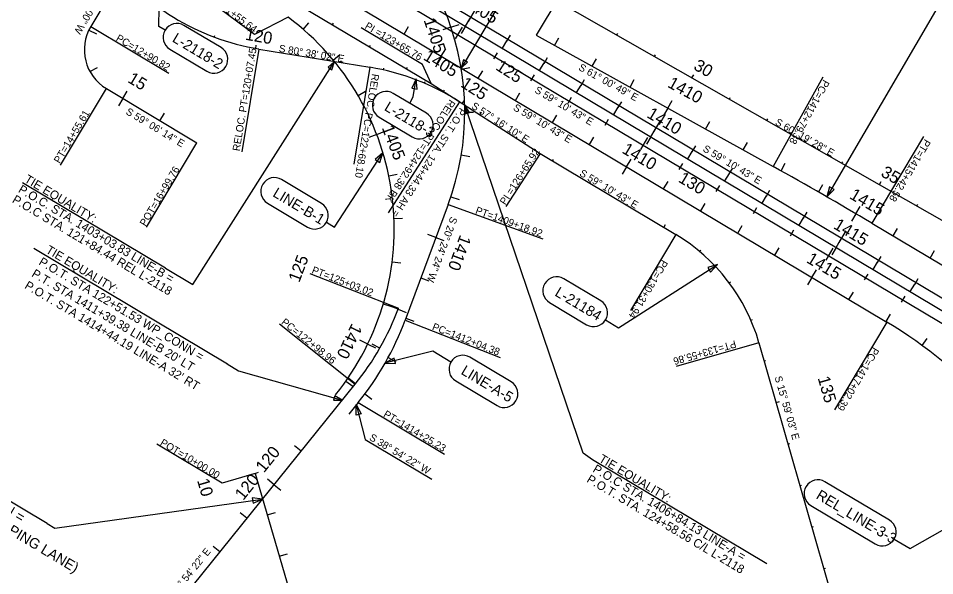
# Model space of a CAD drawing. Extents: x 2339300 to 2355400, y 360879 to 381052.
# Drawn here: x 2345923 to 2348046, y 368208 to 369499 of the extents above; entities that cross this region are included whole.
import ezdxf

# ---------------------------------------------------------------- set-up
doc = ezdxf.new("R2010")
doc.units = 0
for name, color, linetype in [('RD_HC_Cl', 7, 'Continuous'), ('RD_HC_CL_Rel', 7, 'Continuous'), ('RD_HC_Data', 7, 'Continuous'), ('RD_HC_Data_Rel', 7, 'Continuous'), ('RD_HC_Data_Tic', 7, 'Continuous'), ('RD_HC_Data_Tic_Rel', 7, 'Continuous'), ('RD_HC_TX_Rel_Sta50', 7, 'Continuous'), ('RD_HC_TX_Sta50', 7, 'Continuous'), ('RD_PD_Final_TX', 7, 'Continuous')]:
    doc.layers.add(name, color=color, linetype=linetype)

msp = doc.modelspace()

# ---------------------------------------------------------------- linework, layer by layer
at = {"layer": 'RD_HC_Cl'}
for p, q in [((2346281.6, 369885.4), (2351112.4, 367003.2)), ((2346202.2, 369752.3), (2346879.4, 369348.3)), ((2346240, 369730), (2346091, 369480.3)), ((2347125.2, 369566.1), (2348362.6, 368861)), ((2346879.4, 369348.3), (2347131.9, 369186)), ((2346127.3, 369336.4), (2346336.8, 369211)), ((2347131.9, 369186), (2347446.2, 368998.5)), ((2346919, 369067.9), (2346819.4, 368800.4)), ((2347639.2, 368747.8), (2347994.6, 367509.7)), ((2346059.3, 367853.2), (2346703.6, 368651.5)), ((2346710.6, 368609.3), (2346688.9, 368582.4)), ((2346471.7, 368445.2), (2346829.6, 367219.9))]:
    msp.add_line(p, q, dxfattribs=at)
for centre, radius, start, end in [((2346341.6, 369282.7), 616, 339.5935, 61.7249), ((2346182, 369011.6), 612, 321.0938, 53.1918), ((2346181.2, 369426.5), 105, 149.1832, 239.1039), ((2347225.9, 368629.2), 430, 16.0174, 59.1785), ((2346211.8, 369048.5), 632, 321.0938, 339.5935), ((2346178.4, 369038.9), 684, 321.0938, 339.5935)]:
    msp.add_arc(centre, radius, start, end, dxfattribs=at)
at = {"layer": 'RD_HC_CL_Rel'}
for p, q in [((2346294.5, 369907), (2348311.8, 368703.5)), ((2346268.7, 369863.8), (2348286, 368660.2)), ((2346236.3, 369809.5), (2347935.6, 368795.6)), ((2347122.8, 369460.4), (2347672.4, 369155.9)), ((2346480.4, 369428.2), (2346737.6, 369385.8)), ((2347900.5, 369024.7), (2348345.9, 368759))]:
    msp.add_line(p, q, dxfattribs=at)
for centre, radius, start, end in [((2346569.9, 369970.9), 550, 216.3291, 260.6339), ((2346648.1, 368843.1), 550, 57.2694, 80.6339), ((2343690.2, 361967.9), 8217.3, 59.17851, 61.01367), ((2347423.3, 367936.8), 1000, 22.7108, 59.1785)]:
    msp.add_arc(centre, radius, start, end, dxfattribs=at)
at = {"layer": 'RD_HC_Data'}
for p, q in [((2346091, 369480.3), (2346272.3, 369372.1)), ((2346392.9, 369431.6), (2346307, 369482.8)), ((2346274.2, 369427.8), (2346360.1, 369376.6)), ((2346021.1, 369158.8), (2346127.3, 369336.4)), ((2346868.7, 369279.4), (2346791.7, 369325.3)), ((2346759, 369270.3), (2346835.9, 369224.4)), ((2346220, 369015.9), (2346336.8, 369211)), ((2347131.9, 369186), (2347053, 369063.3)), ((2346625.8, 369070.7), (2346533.3, 369125.9)), ((2346500.5, 369070.9), (2346593, 369015.7)), ((2346919, 369067.9), (2347138.3, 368988.5)), ((2347446.2, 368998.5), (2347341.3, 368822.7)), ((2346598.4, 368908.4), (2346804.1, 368828.1)), ((2347272.7, 368844.6), (2347186.9, 368895.8)), ((2347154.1, 368840.9), (2347239.9, 368789.6)), ((2346528.2, 368791.8), (2346703.6, 368651.5)), ((2346819.4, 368800.4), (2347039.4, 368713.6)), ((2347639.2, 368747.8), (2347447.5, 368692.8)), ((2347065.1, 368657.1), (2346969.4, 368714.2)), ((2346936.6, 368659.2), (2347032.3, 368602.1)), ((2345990, 368328.8), (2345468, 368640.3)), ((2346710.6, 368609.3), (2346910.7, 368489.9)), ((2347941.4, 368336.9), (2347792.1, 368426)), ((2347759.3, 368371), (2347908.6, 368282))]:
    msp.add_line(p, q, dxfattribs=at)
for points in [[(2348132.2, 369559.9), (2348088.1, 369586.2), (2347796.2, 369085.9)], [(2346548.7, 369501.6), (2346470.5, 369461.8), (2346330.5, 369566.4)], [(2346263.1, 369471.7), (2346249, 369480.1), (2346249.8, 369523.6)], [(2346879.4, 369348.3), (2346859.9, 369392.4), (2346717.9, 369477.1)], [(2346830.2, 369302.3), (2346837.9, 369318.4), (2346844.8, 369359.3)], [(2346636.9, 369026.8), (2346655.9, 369015.4), (2346768, 369188)], [(2347283.8, 368800.7), (2347314, 368782.7), (2347543.3, 368929.1)], [(2346925.5, 368703.1), (2346883.5, 368728.1), (2346772.7, 368700.4)], [(2346705.6, 368604.6), (2346726.9, 368523.7), (2346881.3, 368431.6)], [(2346471.7, 368445.2), (2346395.4, 368422.5), (2346244.4, 368512.6)], [(2347952.5, 368293), (2347989.6, 368270.9), (2348287.4, 368440)], [(2345990, 368328.8), (2346008.1, 368318.1), (2346489.1, 368385.7)]]:
    msp.add_lwpolyline(points, dxfattribs=at)
for points in [[(2346847.1, 369335.4), (2346844.8, 369359.3), (2346834.8, 369337.4)], [(2346760.6, 369165.2), (2346768, 369188), (2346750.2, 369171.9)], [(2347802.6, 369109), (2347796.2, 369085.9), (2347813.3, 369102.8)], [(2347527.1, 368911.4), (2347543.3, 368929.1), (2347520.4, 368921.9)], [(2346793.7, 368712), (2346772.7, 368700.4), (2346796.7, 368700)], [(2346467, 368376.3), (2346489.1, 368385.7), (2346465.2, 368388.6)]]:
    msp.add_lwpolyline(points, close=True, dxfattribs=at)
for centre, start, end in [((2346290.6, 369455.3), 59.1784, 239.1784), ((2346376.5, 369404.1), 239.1784, 59.1784), ((2346775.4, 369297.8), 59.1784, 239.1784), ((2346852.3, 369251.9), 239.1784, 59.1784), ((2346516.9, 369098.4), 59.1784, 239.1784), ((2346609.4, 369043.2), 239.1784, 59.1784), ((2347170.5, 368868.4), 59.1784, 239.1784), ((2347256.3, 368817.1), 239.1784, 59.1784), ((2346953, 368686.7), 59.1784, 239.1784), ((2347048.7, 368629.6), 239.1784, 59.1784), ((2347775.7, 368398.5), 59.1784, 239.1784), ((2347925, 368309.4), 239.1784, 59.1784)]:
    msp.add_arc(centre, 32, start, end, dxfattribs=at)
at = {"layer": 'RD_HC_Data_Rel'}
for p, q in [((2346480.4, 369428.2), (2346441.1, 369189.9)), ((2346737.6, 369385.8), (2346700.6, 369161.6)), ((2347786.9, 369362.7), (2347672.4, 369155.9)), ((2346945.5, 369305.8), (2346780.4, 369048.9)), ((2348020.2, 369225.4), (2347900.5, 369024.7)), ((2347935.6, 368795.6), (2347814.5, 368592.6))]:
    msp.add_line(p, q, dxfattribs=at)
at = {"layer": 'RD_HC_Data_Tic'}
for p, q in [((2346959.2, 369481.1), (2346969.5, 369498.3)), ((2346086.7, 369472.2), (2346104.7, 369463.5)), ((2346583.2, 369473.7), (2346596.3, 369488.8)), ((2346651.1, 369484.4), (2346653.2, 369487.9)), ((2346925.6, 369478.8), (2346906.6, 369472.4)), ((2346925.6, 369478.8), (2346944.6, 369485.1)), ((2346959.2, 369481.1), (2346949, 369464)), ((2347310.2, 369460.7), (2347312.2, 369464.1)), ((2346737, 369433.2), (2346739.1, 369436.6)), ((2347045.1, 369429.9), (2347055.3, 369447.1)), ((2346653, 369402.3), (2346668.4, 369415.1)), ((2347397.1, 369411.2), (2347399.1, 369414.6)), ((2347131, 369378.7), (2347141.2, 369395.8)), ((2346089.2, 369375.9), (2346106.7, 369385.6)), ((2346822.9, 369382), (2346824.9, 369385.4)), ((2346949.6, 369381.8), (2346969.3, 369385)), ((2347484, 369361.6), (2347487.9, 369368.6)), ((2347216.8, 369327.4), (2347227.1, 369344.6)), ((2346165.4, 369313.6), (2346175.7, 369330.7)), ((2346710.3, 369320.5), (2346727.6, 369330.6)), ((2346908.2, 369329.8), (2346910.3, 369333.1)), ((2346165.4, 369313.6), (2346155.1, 369296.4)), ((2347570.8, 369312.1), (2347572.8, 369315.6)), ((2346957.6, 369282.2), (2346977.6, 369282.2)), ((2346992.3, 369275.7), (2346996.6, 369282.4)), ((2347302.7, 369276.2), (2347313, 369293.4)), ((2346251.2, 369262.2), (2346261.5, 369279.4)), ((2347657.7, 369262.6), (2347659.7, 369266.1)), ((2346753.5, 369230.4), (2346772.2, 369237.6)), ((2347388.6, 369225), (2347398.8, 369242.1)), ((2346753.5, 369230.4), (2346734.9, 369223.3)), ((2347076.4, 369221.6), (2347078.6, 369225)), ((2347388.6, 369225), (2347378.3, 369207.8)), ((2347744.6, 369213.1), (2347746.6, 369216.6)), ((2346949.4, 369182.7), (2346969.2, 369179.4)), ((2347474.5, 369173.7), (2347484.7, 369190.9)), ((2347161.1, 369168.5), (2347163.2, 369172)), ((2347831.5, 369163.6), (2347833.5, 369167.1)), ((2346781.5, 369134.5), (2346801.1, 369138.5)), ((2347560.3, 369122.5), (2347570.6, 369139.7)), ((2347247, 369117.3), (2347249.1, 369120.7)), ((2347918.4, 369114.1), (2347922.3, 369121.1)), ((2346925.3, 369085.7), (2346944.2, 369079.4)), ((2347332.9, 369066.1), (2347334.9, 369069.5)), ((2347646.2, 369071.2), (2347656.5, 369088.4)), ((2348005.3, 369064.6), (2348007.2, 369068.1)), ((2346793.5, 369035.4), (2346813.5, 369036.1)), ((2347732.1, 369020), (2347742.3, 369037.2)), ((2347418.8, 369014.8), (2347422.9, 369021.7)), ((2346890.7, 368991.9), (2346871.9, 368998.9)), ((2346890.7, 368991.9), (2346909.4, 368985)), ((2347818, 368968.8), (2347828.2, 368985.9)), ((2347501.6, 368959.1), (2347504.2, 368962.2)), ((2347818, 368968.8), (2347807.7, 368951.6)), ((2346789.3, 368935.6), (2346809.1, 368933.1)), ((2347903.9, 368917.5), (2347914.1, 368934.7)), ((2346855.8, 368898.2), (2346874.6, 368891.2)), ((2347570.3, 368886.7), (2347573.5, 368889.1)), ((2347989.7, 368866.3), (2348000, 368883.5)), ((2346768.8, 368837.8), (2346788, 368832.1)), ((2346803.1, 368825.3), (2346784.4, 368832.3)), ((2346803.1, 368825.3), (2346821.8, 368818.2)), ((2346821, 368804.5), (2346839.7, 368797.5)), ((2347620.3, 368800.4), (2347624, 368802)), ((2346732.7, 368744.6), (2346714.7, 368753.4)), ((2346732.7, 368744.6), (2346750.7, 368735.9)), ((2346760.5, 368734.9), (2346743.2, 368744.8)), ((2346779.9, 368713.4), (2346797.5, 368703.9)), ((2347651.4, 368705.4), (2347655.2, 368706.5)), ((2346704.3, 368652.4), (2346688.7, 368664.9)), ((2346682, 368658.6), (2346698.3, 368647.1)), ((2346726.1, 368629.2), (2346742.1, 368617.2)), ((2347679, 368609.3), (2347686.6, 368611.5)), ((2346578.7, 368496.7), (2346563.1, 368509.3)), ((2347706.5, 368513.2), (2347710.4, 368514.3)), ((2346471.7, 368445.2), (2346452.5, 368439.6)), ((2346471.7, 368445.2), (2346480, 368447.7)), ((2346515.8, 368418.9), (2346500.3, 368431.5)), ((2346515.8, 368418.9), (2346531.4, 368406.3)), ((2347734.1, 368417), (2347738, 368418.2)), ((2346453, 368341.1), (2346437.5, 368353.6)), ((2346499.7, 368349.2), (2346518.9, 368354.8)), ((2347761.7, 368320.9), (2347765.6, 368322)), ((2346390.2, 368263.3), (2346374.7, 368275.8)), ((2346527.7, 368253.2), (2346546.9, 368258.9)), ((2347789.3, 368224.8), (2347793.2, 368225.9))]:
    msp.add_line(p, q, dxfattribs=at)
at = {"layer": 'RD_HC_Data_Tic_Rel'}
for p, q in [((2346966.3, 369492.2), (2346982.7, 369519.7)), ((2346817.2, 369462.9), (2346827.4, 369480.1)), ((2346936.1, 369451.7), (2346952.5, 369479.1)), ((2346376.8, 369455.9), (2346378.2, 369459.7)), ((2347055.3, 369446.1), (2347063.5, 369459.9)), ((2347165.6, 369436.7), (2347175.2, 369454.2)), ((2346473.1, 369429.5), (2346474.5, 369437.4)), ((2346903.1, 369411.7), (2346913.3, 369428.8)), ((2346571.7, 369413.2), (2346572.4, 369417.1)), ((2346903.1, 369411.7), (2346892.8, 369394.5)), ((2347025, 369405.6), (2347033.2, 369419.3)), ((2347141.2, 369394.9), (2347149.4, 369408.6)), ((2346670.4, 369396.9), (2346671, 369400.8)), ((2347253, 369388.2), (2347262.7, 369405.7)), ((2346768.9, 369379.7), (2346769.8, 369383.6)), ((2346988.9, 369360.4), (2346999.2, 369377.6)), ((2347110.9, 369354.3), (2347119.1, 369368.1)), ((2346863.9, 369349), (2346865.5, 369352.7)), ((2347227, 369343.7), (2347235.2, 369357.4)), ((2347340.5, 369339.8), (2347350.2, 369357.3)), ((2347074.8, 369309.2), (2347085.1, 369326.4)), ((2346951.9, 369301.7), (2346956.2, 369308.4)), ((2347196.8, 369303.1), (2347205, 369316.8)), ((2347312.9, 369292.4), (2347321.1, 369306.2)), ((2347428, 369291.3), (2347437.7, 369308.8)), ((2347428, 369291.3), (2347418.3, 369273.8)), ((2347160.7, 369258), (2347170.9, 369275.1)), ((2347282.7, 369251.9), (2347290.9, 369265.6)), ((2347395.7, 369236), (2347412.1, 369263.5)), ((2347515.4, 369242.9), (2347525.1, 369260.4)), ((2347246.6, 369206.7), (2347256.8, 369223.9)), ((2347365.5, 369195.5), (2347381.9, 369222.9)), ((2347484.7, 369189.9), (2347492.9, 369203.7)), ((2347602.9, 369194.4), (2347612.6, 369211.9)), ((2347332.4, 369155.5), (2347322.2, 369138.3)), ((2347332.4, 369155.5), (2347342.7, 369172.7)), ((2347454.4, 369149.4), (2347462.6, 369163.1)), ((2347570.5, 369138.7), (2347578.7, 369152.5)), ((2347690.4, 369145.9), (2347700.1, 369163.4)), ((2347418.3, 369104.3), (2347428.6, 369121.4)), ((2347540.3, 369098.1), (2347548.5, 369111.9)), ((2347777.4, 369096.7), (2347787.4, 369114.1)), ((2347656.4, 369087.5), (2347664.6, 369101.2)), ((2347504.2, 369053), (2347514.4, 369070.2)), ((2347626.2, 369046.9), (2347634.4, 369060.7)), ((2347742.3, 369036.2), (2347750.5, 369050)), ((2347863.9, 369046.4), (2347853.7, 369029.2)), ((2347863.9, 369046.4), (2347874, 369063.7)), ((2347590.1, 369001.8), (2347600.3, 369019)), ((2347712, 368995.7), (2347720.2, 369009.4)), ((2347825.1, 368979.8), (2347841.5, 369007.3)), ((2347949.8, 368995.3), (2347960.1, 369012.5)), ((2347676, 368950.5), (2347686.2, 368967.7)), ((2347794.8, 368939.3), (2347811.2, 368966.8)), ((2347914.1, 368933.8), (2347922.2, 368947.5)), ((2348035.7, 368944.1), (2348045.9, 368961.2)), ((2347761.8, 368899.3), (2347751.6, 368882.1)), ((2347761.8, 368899.3), (2347772.1, 368916.5)), ((2347883.8, 368893.2), (2347892, 368906.9)), ((2347999.9, 368882.5), (2348008.1, 368896.3)), ((2347847.7, 368848.1), (2347858, 368865.2)), ((2347969.7, 368842), (2347977.9, 368855.7)), ((2347933.6, 368796.8), (2347943.8, 368814)), ((2348016.9, 368741.6), (2348028.8, 368757.7))]:
    msp.add_line(p, q, dxfattribs=at)
at = {"layer": 'RD_PD_Final_TX'}
for p, q in [((2346264.5, 368920.6), (2345932.7, 369118.6)), ((2346408.2, 368698.1), (2345958.9, 368966.2)), ((2347657.5, 368235.8), (2347253.8, 368476.7))]:
    msp.add_line(p, q, dxfattribs=at)
for points in [[(2347563.3, 370325.1), (2347524.2, 370348.4), (2346949.2, 369384.1)], [(2347617.1, 370115.2), (2347543.4, 370159.2), (2347122.8, 369460.4)], [(2346264.5, 368920.6), (2346327.7, 368882.9), (2346655.5, 369399.3)], [(2347253.8, 368476.7), (2347232.2, 368491.8), (2346957.4, 369298.1)], [(2346407.2, 368698.7), (2346433.5, 368683), (2346673.8, 368614.6)]]:
    msp.add_lwpolyline(points, dxfattribs=at)
for points in [[(2346649.5, 369380.3), (2346655.5, 369399.3), (2346640.8, 369385.8)], [(2346954.7, 369403.4), (2346949.2, 369384.1), (2346963.6, 369398.1)], [(2346968.6, 369281.5), (2346957.4, 369298.1), (2346958.8, 369278.1)], [(2346653.8, 368614.9), (2346673.8, 368614.6), (2346656.7, 368624.9)], [(2346705.9, 368579.9), (2346705.6, 368604.6), (2346717.5, 368582.9)]]:
    msp.add_lwpolyline(points, close=True, dxfattribs=at)

# ---------------------------------------------------------------- texts
at = {"layer": 'RD_HC_Data'}
for s, height, rotation, p in [('S 30%%d 49\' 00" W', 17, 239.1832, (2346133.4, 369606.1)), ('PC=1401+55.64', 17, 323.2956, (2346335.7, 369563.9)), ('PI =123+65.76', 17, 329.1785, (2346724.6, 369477)), ('PC=12+90.82', 17, 329.1832, (2346147.9, 369448.7)), ('L-2118-2', 24, 329.1784, (2346278, 369446.5)), ('L-2118-3', 24, 329.1784, (2346769.2, 369287.5)), ('S 57%%d 16\' 10" E', 17, 327.2694, (2346971.2, 369292)), ('PT=14+55.61', 17, 59.1039, (2346018.8, 369161.7)), ('S 59%%d 06\' 14" E', 17, 329.1039, (2346170.6, 369278.5)), ('S 60%%d 19\' 28" E', 17, 330.3243, (2347675, 369253.9)), ('PI =126+65.92', 17, 57.2694, (2347051.6, 369065.6)), ('POT=16+99.76', 17, 59.1039, (2346217.9, 369016.2)), ('S 59%%d 10\' 43" E', 17, 329.1785, (2347221.7, 369136)), ('LINE-B-1', 24, 329.1784, (2346510.8, 369088.1)), ('PT=1409+18.92', 17, 340.0882, (2346980.8, 369047.7)), ('S 20%%d 24\' 24" W', 17, 249.5935, (2346925, 369041.2)), ('PT=125+03.02', 17, 338.6648, (2346601.6, 368909.6)), ('PC=130+31.94', 17, 239.1785, (2347414.6, 368941.6)), ('L-21184', 24, 329.1784, (2347164.3, 368858)), ('PC=122+98.96', 17, 321.3534, (2346531, 368792.7)), ('PC=1412+04.38', 17, 338.4746, (2346880.6, 368778.4)), ('PT=133+55.86', 17, 196.0174, (2347583.5, 368753.7)), ('LINE-A-5', 24, 329.1784, (2346946.9, 368676.4)), ('P.O.T. STA. 119+57.33 WP_CONN =', 24, 329.1784, (2345469.8, 368604.3)), ('P.O.T. STA. 10+62.02 L-8661 (SHIPPING LANE)', 24, 329.1784, (2345451.3, 368573.4)), ('PT=1414+25.23', 17, 329.1784, (2346767.5, 368577.7)), ('POT=10+00.00', 17, 329.1784, (2346250.1, 368511.7)), ('S 38%%d 54\' 22" W', 17, 329.1784, (2346734.8, 368523.7)), ('REL_LINE-3-3', 24, 329.1784, (2347769.6, 368388.2)), ('N 38%%d 54\' 22" E', 17, 51.0938, (2346273.5, 368143.7))]:
    msp.add_text(s, height=height, rotation=rotation, dxfattribs=at).set_placement(p)
at = {"layer": 'RD_HC_Data_Rel'}
for s, rotation, p in [('RELOC. PT=120+07.45', 80.6339, (2346436, 369190.7)), ('S 80%%d 38\' 02" E', 350.6339, (2346526, 369421.7)), ('S 61%%d 00\' 49" E', 331.0137, (2347219.6, 369380.6)), ('RELOC. PC=122+68.10', 260.6339, (2346742.7, 369371.7)), ('PC=1412+79.38', 241.0137, (2347788.7, 369358.5)), ('S 59%%d 10\' 43" E', 329.1785, (2347117.9, 369328.5)), ('RELOC. PT=124+92.38 BK', 237.2694, (2346922.7, 369312.8)), ('P.O.T. STA. 124+44.33 AH =', 237.2694, (2346946.6, 369293.6)), ('S 59%%d 10\' 43" E', 329.1785, (2347068.2, 369287.9)), ('PT=1415+42.58', 239.1785, (2348023.4, 369221)), ('S 59%%d 10\' 43" E', 329.1785, (2347507.6, 369192.5)), ('PC=1417+02.39', 239.1785, (2347904.1, 368738.8)), ('S 15%%d 59\' 03" E', 285.9841, (2347675.2, 368668.1))]:
    msp.add_text(s, height=17, rotation=rotation, dxfattribs=at).set_placement(p)
at = {"layer": 'RD_HC_TX_Rel_Sta50'}
for s, rotation, p in [('120', 349.8574, (2346447.5, 369449.9)), ('1405', 329.1785, (2346859.6, 369404.7)), ('125', 327.2694, (2346946.1, 369342.1)), ('1410', 331.0137, (2347425.4, 369341.3)), ('1410', 329.1785, (2347319.9, 369188.9)), ('1415', 329.4754, (2347847, 369083.3)), ('1415', 329.1785, (2347747.3, 368935))]:
    msp.add_text(s, height=28, rotation=rotation, dxfattribs=at).set_placement(p)
at = {"layer": 'RD_HC_TX_Sta50'}
for s, rotation, p in [('1405', 329.1785, (2346952.6, 369528.2)), ('1405', 288.5579, (2346861.9, 369495.2)), ('125', 327.2694, (2347027.2, 369381.7)), ('30', 330.3243, (2347485.7, 369382.2)), ('15', 329.1039, (2346174.6, 369352.5)), ('1410', 329.1785, (2347377.5, 369271.1)), ('1405', 290.9528, (2346764.9, 369245.9)), ('35', 330.3243, (2347919.6, 369135)), ('130', 329.1785, (2347450.4, 369121.7)), ('1415', 329.1785, (2347809.8, 369013.8)), ('1410', 249.5935, (2346947, 368999.5)), ('125', 69.3199, (2346574.1, 368885.9)), ('1410', 244.1425, (2346696.2, 368794.4)), ('135', 286.0174, (2347775, 368666.2)), ('120', 51.0938, (2346492.3, 368445.2)), ('10', 286.2842, (2346337.1, 368429)), ('120', 51.0938, (2346444.2, 368381.1))]:
    msp.add_text(s, height=28, rotation=rotation, dxfattribs=at).set_placement(p)
at = {"layer": 'RD_PD_Final_TX'}
for s, p in [('TIE EQUALITY:', (2345935.5, 369121.3)), ('P.O.C. STA. 1403+03.83 LINE-B =', (2345921.4, 369097.7)), ('P.O.C STA. 121+84.44 REL L-2118', (2345907.3, 369074.1)), ('TIE EQUALITY:', (2345985.2, 368957.5)), ('P.O.T. STA 122+51.53 WP_CONN =', (2345968.8, 368930)), ("P.T. STA 1411+39.38 LINE-B 20' LT", (2345952.4, 368902.5)), ("P.O.T. STA 1414+44.19 LINE-A 32' RT", (2345936, 368875)), ('TIE EQUALITY:', (2347266.5, 368473.5)), ('P.O.C STA. 1406+84.13 LINE-A =', (2347252.4, 368449.9)), ('P.O.T. STA. 124+58.56 C/L L-2118', (2347238.3, 368426.3))]:
    msp.add_text(s, height=20, rotation=329.1784, dxfattribs=at).set_placement(p)

doc.saveas('drawing.dxf')
